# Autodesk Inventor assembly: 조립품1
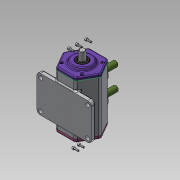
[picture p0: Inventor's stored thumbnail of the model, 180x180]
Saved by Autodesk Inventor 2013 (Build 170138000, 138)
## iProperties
Created: 2021-06
Part Number: 조립품1
Document SubType Name: Assembly
Designer: hana-max10
Author: hana-max10
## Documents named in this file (11)
- C:\Documents and Settings\hana-max10\바탕 화면\710606V1023\조립품1.iam
- C:\Documents and Settings\hana-max10\바탕 화면\710606V1023\부품1.ipt
- C:\Documents and Settings\hana-max10\바탕 화면\710606V1023\710606V1023\앞커버.ipt
- C:\Documents and Settings\hana-max10\바탕 화면\710606V1023\710606V1023\뒷커버.ipt
- C:\Documents and Settings\hana-max10\바탕 화면\710606V1023\710606V1023\부시.ipt
- C:\Documents and Settings\hana-max10\바탕 화면\710606V1023\710606V1023\오일실.ipt
- C:\Documents and Settings\hana-max10\바탕 화면\710606V1023\710606V1023\베어링 6203.ipt
- C:\Documents and Settings\hana-max10\바탕 화면\710606V1023\710606V1023\편심축.ipt
- C:\Documents and Settings\hana-max10\바탕 화면\710606V1023\710606V1023\베어링 6302.ipt
- C:\Documents and Settings\hana-max10\바탕 화면\710606V1023\710606V1023\슬라이더.ipt
- C:\Documents and Settings\hana-max10\바탕 화면\710606V1023\710606V1023\볼트 M4.ipt
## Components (10 placed, 3 different names)
1. 8-오일실:1
2. 7-베어링 6203:1
3. 9-M4-소켓머리:1
4. 9-M4-소켓머리:2
5. 9-M4-소켓머리:3
6. 9-M4-소켓머리:4
7. 9-M4-소켓머리:5
8. 9-M4-소켓머리:6
9. 9-M4-소켓머리:7
10. 9-M4-소켓머리:8
